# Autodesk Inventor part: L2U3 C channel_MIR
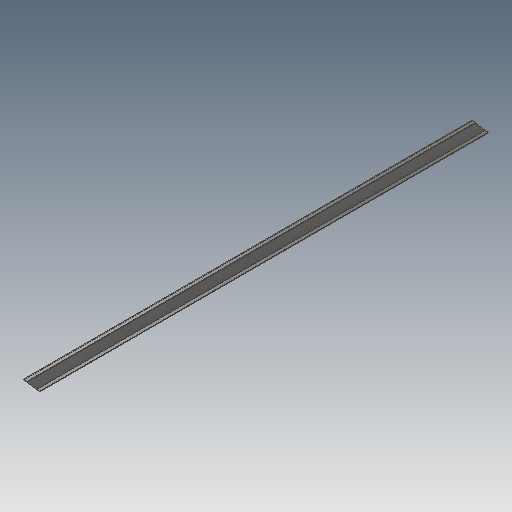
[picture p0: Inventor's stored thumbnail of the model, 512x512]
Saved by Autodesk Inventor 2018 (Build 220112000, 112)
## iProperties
Created: 2018-02
Part Number: L2U3 C channel_MIR
Material: Steel, Mild
Document SubType Name: Modeling
Designer: STK
Density: 7.85 g/cm^3
Appearance: Semi-Polished
Author: STK
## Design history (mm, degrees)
derived "L2U3 C channel.ipt"
  sketch "Sketch1"
    geometry: L1 (-12.7, 177.8)-(-12.7, -177.8) reference; L2 (0, -190.5)-(0, 190.5) reference; L3 (0, -190.5)-(-92.075, -190.5) reference; L4 (-92.075, -190.5)-(-92.075, -177.8) reference; L5 (-92.075, -177.8)-(-12.7, -177.8) reference; L6 (0, 190.5)-(-92.075, 190.5) reference; L7 (-92.075, 190.5)-(-92.075, 177.8) reference; L8 (-92.075, 177.8)-(-12.7, 177.8) reference; L9 (0, 0)-(-92.075, 0) reference
  sketch "Sketch2"
    geometry: L1 (0, 0)-(5134.804, 5915.55) reference; L2 (11430, 381)-(0, 381) reference; L3 (0, 381)-(0, 0) reference; L4 (0, 381)-(330.715, 381) reference; L5 (11430, 381)-(0, 381) reference; L6 (0, 0)-(330.715, 381) reference; L7 (0, 381)-(0, 0) reference; L8 (0, 12.7)-(0, 368.3) reference; 1 further point
  sketch "Sketch3"
    geometry: L1 (-5100.05, -5494.511)-(34.754, 421.039) reference; L2 (0, 0)-(0, 381) reference; L3 (-11430, 0)-(0, 0) reference; L4 (0, 381)-(0, 0) reference; L5 (0, 0)-(-330.715, 0) reference; L6 (0, 381)-(-11099.285, 381) reference; L7 (0, 381)-(-330.715, 0) reference; 1 further point
feature "Solid1::L2U3 C channel.ipt"
tag "TaggingFeature1"
body "Solid1"
